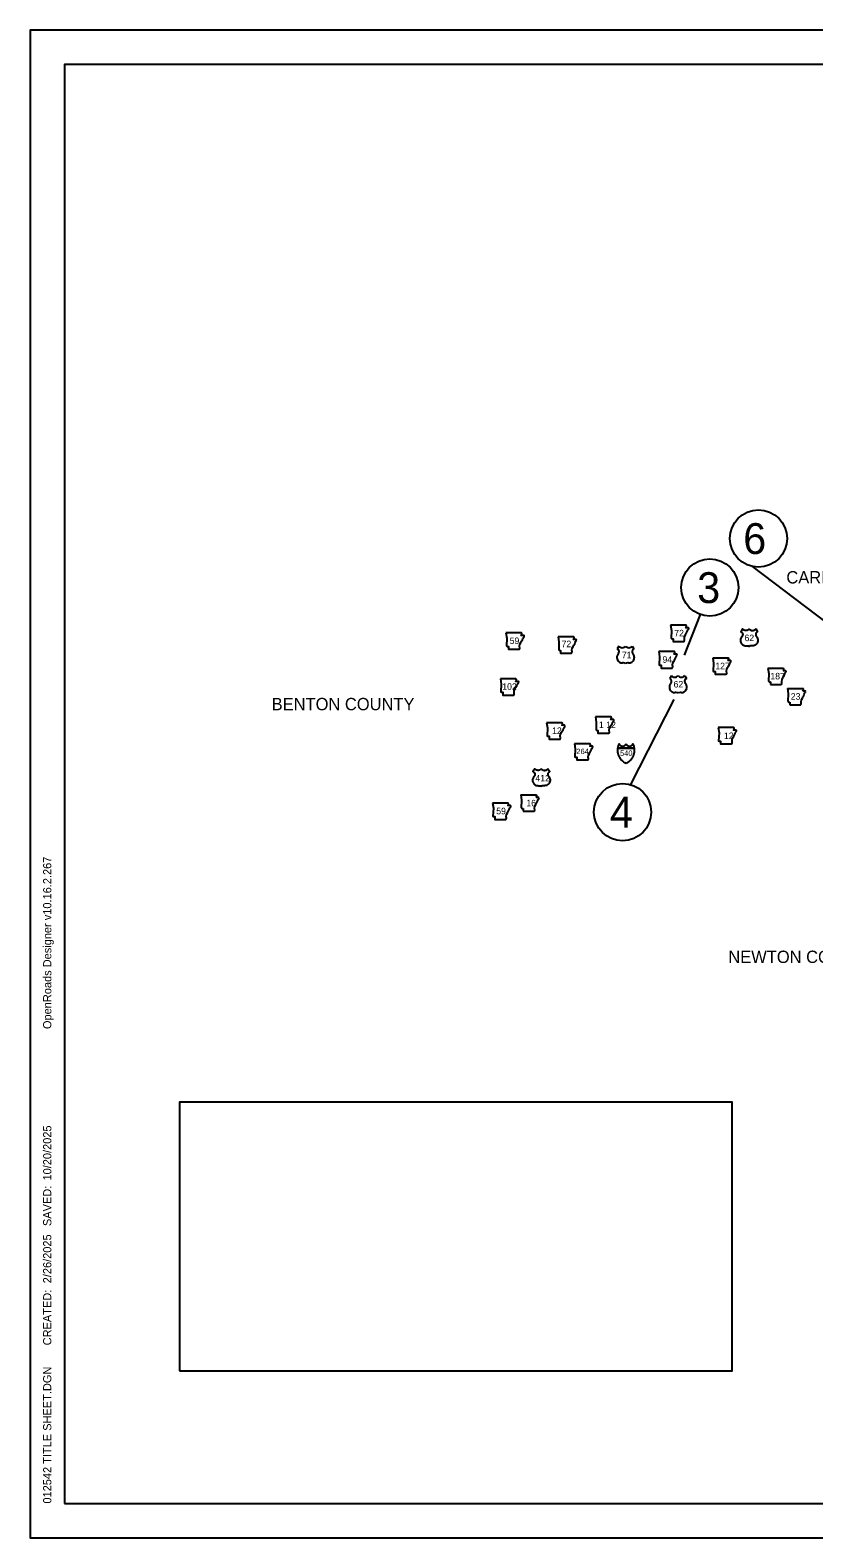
# Model space of a CAD drawing. Extents: x -819161 to 80911, y -6604 to 768454.
# Drawn here: x 35278 to 41002, y -340 to 10660 of the extents above; entities that cross this region are included whole.
import ezdxf

# ---------------------------------------------------------------- set-up
doc = ezdxf.new("R2010")
doc.units = 0
for name, color, linetype in [('Default', 7, 'Continuous'), ('DSN_BRDG_Annotation', 7, 'Continuous'), ('DSN_DRFT_Junk-No-Plot', 7, 'Continuous'), ('Level 21', 7, 'Continuous'), ('Level 22', 7, 'Continuous'), ('Level 23', 7, 'Continuous'), ('SHET_Border-Lines', 7, 'Continuous'), ('SHET_Border-Text', 7, 'Continuous')]:
    doc.layers.add(name, color=color, linetype=linetype)

msp = doc.modelspace()

# ---------------------------------------------------------------- linework, layer by layer
at = {"layer": 'Default'}
msp.add_lwpolyline([(35278, 10660), (35278, -340), (52278, -340), (52278, 10660)], close=True, dxfattribs=at)
for points in [[(40548, 6748), (41494, 6034)], [(40171, 6396), (40054, 6101)], [(39665, 5155), (39981, 5777)]]:
    msp.add_lwpolyline(points, dxfattribs=at)
for centre in [(40597, 6951), (40242, 6593), (39605, 4955)]:
    msp.add_circle(centre, 209, dxfattribs=at)
at = {"layer": 'DSN_BRDG_Annotation'}
msp.add_lwpolyline([(36370, 878), (40406, 878), (40406, 2838), (36370, 2838)], close=True, dxfattribs=at)
at = {"layer": 'DSN_DRFT_Junk-No-Plot'}
msp.add_lwpolyline([(35278, -340), (52278, -340), (52278, 10660), (35278, 10660)], close=True, dxfattribs=at)
at = {"layer": 'Level 21'}
for p, q in [((40666, 6004), (40672, 5966)), ((40672, 5966), (40670, 5909)), ((40776, 5934), (40780, 5943)), ((40778, 5985), (40783, 5994)), ((40798, 5985), (40778, 5985)), ((40780, 5943), (40786, 5952)), ((40783, 6000), (40781, 6004)), ((40783, 5994), (40783, 6000)), ((40786, 5952), (40790, 5963)), ((40790, 5963), (40793, 5971)), ((40793, 5971), (40799, 5978)), ((40800, 5982), (40798, 5985)), ((40799, 5978), (40800, 5982)), ((40670, 5909), (40675, 5906)), ((40675, 5906), (40684, 5906)), ((40684, 5906), (40684, 5885)), ((40684, 5885), (40764, 5885)), ((40764, 5885), (40768, 5893)), ((40767, 5907), (40769, 5922)), ((40768, 5893), (40767, 5907)), ((40769, 5922), (40776, 5934)), ((40809, 5857), (40814, 5819)), ((40920, 5838), (40925, 5847)), ((40940, 5838), (40920, 5838)), ((40925, 5853), (40923, 5857)), ((40925, 5847), (40925, 5853)), ((40936, 5824), (40941, 5831)), ((40943, 5835), (40940, 5838)), ((40941, 5831), (40943, 5835)), ((40814, 5819), (40812, 5762)), ((40812, 5762), (40817, 5758)), ((40817, 5758), (40826, 5758)), ((40826, 5758), (40826, 5738)), ((40826, 5738), (40906, 5738)), ((40906, 5738), (40910, 5746)), ((40909, 5760), (40911, 5775)), ((40910, 5746), (40909, 5760)), ((40911, 5775), (40918, 5787)), ((40918, 5787), (40922, 5796)), ((40922, 5796), (40929, 5805)), ((40929, 5805), (40932, 5816)), ((40932, 5816), (40936, 5824)), ((38862, 5081), (38867, 5043)), ((38973, 5062), (38978, 5071)), ((38993, 5062), (38973, 5062)), ((38978, 5077), (38976, 5081)), ((38978, 5071), (38978, 5077)), ((38996, 5059), (38993, 5062)), ((38867, 5043), (38865, 4985)), ((38865, 4985), (38870, 4982)), ((38870, 4982), (38879, 4982)), ((38879, 4982), (38879, 4962)), ((38879, 4962), (38959, 4962)), ((38959, 4962), (38963, 4970)), ((38962, 4983), (38964, 4999)), ((38963, 4970), (38962, 4983)), ((38964, 4999), (38971, 5011)), ((38971, 5011), (38975, 5019)), ((38975, 5019), (38982, 5029)), ((38982, 5029), (38985, 5039)), ((38985, 5039), (38989, 5047)), ((38989, 5047), (38994, 5054)), ((38994, 5054), (38996, 5059))]:
    msp.add_line(p, q, dxfattribs=at)
for points in [[(39955, 6319), (39961, 6281), (39959, 6223), (39964, 6220), (39973, 6220), (39973, 6199), (40053, 6199), (40057, 6208), (40056, 6221), (40058, 6236), (40065, 6248), (40069, 6257), (40075, 6267), (40079, 6277), (40082, 6285), (40088, 6292), (40089, 6296), (40087, 6300), (40067, 6300), (40072, 6308), (40072, 6314), (40070, 6319)], [(38753, 6263), (38759, 6225), (38756, 6167), (38761, 6164), (38771, 6164), (38771, 6143), (38851, 6143), (38855, 6152), (38853, 6165), (38855, 6180), (38862, 6192), (38867, 6201), (38873, 6211), (38877, 6221), (38880, 6229), (38886, 6236), (38887, 6240), (38885, 6244), (38865, 6244), (38869, 6252), (38870, 6258), (38867, 6263)], [(39135, 6234), (39140, 6196), (39138, 6138), (39143, 6135), (39152, 6135), (39152, 6114), (39232, 6114), (39236, 6123), (39235, 6136), (39237, 6151), (39244, 6163), (39248, 6172), (39255, 6182), (39258, 6192), (39262, 6200), (39267, 6207), (39268, 6212), (39266, 6215), (39246, 6215), (39251, 6224), (39251, 6229), (39249, 6234)], [(39870, 6126), (39875, 6088), (39873, 6030), (39878, 6027), (39887, 6027), (39887, 6006), (39967, 6006), (39971, 6015), (39970, 6028), (39972, 6043), (39979, 6055), (39983, 6064), (39989, 6074), (39993, 6084), (39996, 6092), (40002, 6099), (40003, 6103), (40001, 6107), (39981, 6107), (39986, 6116), (39986, 6121), (39984, 6126)], [(40263, 6079), (40269, 6041), (40266, 5983), (40271, 5980), (40281, 5980), (40281, 5960), (40361, 5960), (40365, 5968), (40363, 5982), (40365, 5997), (40372, 6009), (40377, 6018), (40383, 6027), (40387, 6037), (40390, 6046), (40396, 6053), (40397, 6057), (40394, 6060), (40375, 6060), (40379, 6069), (40380, 6075), (40377, 6079)], [(38712, 5928), (38718, 5889), (38715, 5832), (38720, 5829), (38730, 5829), (38730, 5808), (38810, 5808), (38813, 5816), (38812, 5830), (38814, 5845), (38821, 5857), (38825, 5866), (38832, 5875), (38836, 5886), (38839, 5894), (38844, 5901), (38846, 5905), (38843, 5908), (38824, 5908), (38828, 5917), (38829, 5923), (38826, 5927)], [(39408, 5650), (39413, 5612), (39411, 5555), (39416, 5551), (39425, 5551), (39425, 5531), (39505, 5531), (39509, 5539), (39508, 5553), (39510, 5568), (39517, 5580), (39521, 5589), (39528, 5598), (39531, 5609), (39535, 5617), (39540, 5624), (39541, 5628), (39539, 5631), (39519, 5631), (39524, 5640), (39524, 5646), (39522, 5650)], [(39050, 5607), (39056, 5569), (39053, 5511), (39058, 5508), (39068, 5508), (39068, 5488), (39148, 5488), (39152, 5496), (39150, 5509), (39152, 5525), (39159, 5537), (39164, 5545), (39170, 5555), (39174, 5565), (39177, 5573), (39183, 5580), (39184, 5585), (39181, 5588), (39162, 5588), (39166, 5597), (39167, 5603), (39164, 5607)], [(40303, 5571), (40309, 5533), (40306, 5475), (40312, 5472), (40321, 5472), (40321, 5452), (40401, 5452), (40405, 5460), (40404, 5474), (40405, 5489), (40412, 5501), (40417, 5510), (40423, 5519), (40427, 5529), (40430, 5538), (40436, 5545), (40437, 5549), (40435, 5552), (40415, 5552), (40419, 5561), (40420, 5567), (40417, 5571)], [(39254, 5454), (39259, 5416), (39257, 5358), (39262, 5355), (39271, 5355), (39271, 5335), (39351, 5335), (39355, 5343), (39354, 5356), (39356, 5371), (39363, 5383), (39367, 5392), (39373, 5402), (39377, 5412), (39380, 5420), (39386, 5427), (39387, 5432), (39385, 5435), (39365, 5435), (39370, 5444), (39370, 5449), (39368, 5454)], [(38655, 5021), (38661, 4983), (38658, 4925), (38663, 4922), (38673, 4922), (38673, 4901), (38753, 4901), (38756, 4910), (38755, 4923), (38757, 4938), (38764, 4950), (38769, 4959), (38775, 4969), (38779, 4979), (38782, 4987), (38788, 4994), (38789, 4998), (38786, 5002), (38767, 5002), (38771, 5011), (38772, 5016), (38769, 5021)]]:
    msp.add_lwpolyline(points, close=True, dxfattribs=at)
for points in [[(40666, 6004), (40781, 6004)], [(40809, 5857), (40923, 5857)], [(38862, 5081), (38976, 5081)]]:
    msp.add_lwpolyline(points, dxfattribs=at)
at = {"layer": 'Level 22'}
for p, q in [((39578, 6166), (39565, 6146)), ((39675, 6166), (39688, 6146)), ((39962, 5950), (39949, 5930)), ((40059, 5950), (40071, 5930))]:
    msp.add_line(p, q, dxfattribs=at)
for points in [[(40529, 6291), (40529, 6290), (40528, 6289), (40526, 6288), (40525, 6287), (40524, 6286), (40523, 6285), (40521, 6284), (40520, 6283), (40518, 6282), (40516, 6282), (40514, 6281), (40513, 6281), (40511, 6280), (40509, 6280), (40508, 6280), (40506, 6280), (40504, 6280), (40503, 6280), (40501, 6280), (40500, 6280), (40498, 6281), (40497, 6281), (40495, 6282), (40493, 6282), (40491, 6283), (40490, 6284), (40489, 6284), (40487, 6285), (40486, 6286), (40485, 6287), (40484, 6288), (40483, 6289), (40482, 6290), (40481, 6291), (40468, 6271), (40469, 6270), (40470, 6270), (40471, 6269), (40473, 6268), (40474, 6267), (40475, 6266), (40476, 6265), (40477, 6264), (40478, 6263), (40478, 6262), (40479, 6261), (40480, 6260), (40480, 6259), (40481, 6257), (40481, 6255), (40482, 6254), (40482, 6252), (40482, 6251), (40482, 6249), (40482, 6248), (40482, 6247), (40481, 6246), (40481, 6244), (40481, 6243), (40480, 6242), (40479, 6240), (40478, 6238), (40477, 6237), (40476, 6236), (40475, 6234), (40474, 6233), (40473, 6231), (40472, 6230), (40472, 6229), (40471, 6227), (40470, 6226), (40469, 6224), (40469, 6223), (40468, 6222), (40468, 6220), (40467, 6218), (40467, 6216), (40466, 6214), (40466, 6213), (40466, 6211), (40466, 6209), (40466, 6207), (40466, 6205), (40466, 6203), (40466, 6201), (40467, 6199), (40467, 6198), (40468, 6197), (40468, 6195), (40469, 6192), (40470, 6191), (40471, 6189), (40471, 6187), (40473, 6185), (40474, 6183), (40475, 6182), (40477, 6180), (40478, 6178), (40480, 6177), (40481, 6176)], [(40529, 6291), (40530, 6290), (40531, 6289), (40532, 6288), (40534, 6287), (40535, 6286), (40536, 6285), (40538, 6284), (40539, 6283), (40541, 6282), (40543, 6282), (40545, 6281), (40546, 6281), (40548, 6280), (40550, 6280), (40551, 6280), (40553, 6280), (40555, 6280), (40556, 6280), (40558, 6280), (40559, 6280), (40561, 6281), (40562, 6281), (40564, 6282), (40566, 6282), (40568, 6283), (40569, 6284), (40570, 6284), (40572, 6285), (40573, 6286), (40574, 6287), (40575, 6288), (40576, 6289), (40577, 6290), (40578, 6291), (40591, 6271), (40590, 6270), (40589, 6270), (40588, 6269), (40586, 6268), (40585, 6267), (40584, 6266), (40583, 6265), (40582, 6264), (40581, 6263), (40581, 6262), (40580, 6261), (40579, 6260), (40579, 6259), (40578, 6257), (40578, 6255), (40577, 6254), (40577, 6252), (40577, 6251), (40577, 6249), (40577, 6248), (40577, 6247), (40578, 6246), (40578, 6244), (40578, 6243), (40579, 6242), (40580, 6240), (40581, 6238), (40582, 6237), (40583, 6236), (40584, 6234), (40585, 6233), (40586, 6231), (40587, 6230), (40587, 6229), (40588, 6227), (40589, 6226), (40590, 6224), (40590, 6223), (40591, 6222), (40591, 6220), (40592, 6218), (40592, 6216), (40593, 6214), (40593, 6213), (40593, 6211), (40593, 6209), (40593, 6207), (40593, 6205), (40593, 6203), (40593, 6201), (40592, 6199), (40592, 6198), (40591, 6197), (40591, 6195), (40590, 6192), (40589, 6191), (40588, 6189), (40587, 6187), (40586, 6185), (40585, 6183), (40584, 6182), (40582, 6180), (40581, 6178), (40579, 6177), (40578, 6176)], [(40481, 6176), (40483, 6174), (40485, 6173), (40488, 6172), (40490, 6171), (40493, 6170), (40495, 6170), (40497, 6169), (40499, 6169), (40502, 6168), (40505, 6168), (40507, 6168), (40509, 6168), (40511, 6168), (40513, 6168), (40515, 6168), (40517, 6168), (40518, 6167), (40520, 6167), (40522, 6167), (40523, 6167), (40524, 6167), (40525, 6166), (40526, 6166), (40527, 6165), (40528, 6165), (40528, 6164), (40529, 6163), (40529, 6162)], [(40578, 6176), (40576, 6174), (40574, 6173), (40571, 6172), (40569, 6171), (40566, 6170), (40564, 6170), (40562, 6169), (40560, 6169), (40557, 6168), (40554, 6168), (40552, 6168), (40550, 6168), (40548, 6168), (40546, 6168), (40544, 6168), (40542, 6168), (40541, 6167), (40539, 6167), (40537, 6167), (40536, 6167), (40535, 6167), (40534, 6166), (40533, 6166), (40532, 6165), (40531, 6165), (40531, 6164), (40530, 6163), (40529, 6162)], [(39012, 5271), (39011, 5269), (39010, 5268), (39009, 5267), (39007, 5266), (39006, 5266), (39005, 5265), (39004, 5264), (39002, 5263), (39000, 5262), (38998, 5261), (38996, 5261), (38995, 5260), (38993, 5260), (38992, 5260), (38990, 5259), (38988, 5259), (38986, 5259), (38985, 5259), (38984, 5260), (38982, 5260), (38980, 5260), (38979, 5261), (38977, 5261), (38975, 5262), (38974, 5263), (38972, 5263), (38971, 5264), (38969, 5265), (38968, 5266), (38967, 5267), (38966, 5268), (38965, 5269), (38964, 5270), (38963, 5271), (38950, 5251), (38951, 5250), (38952, 5249), (38953, 5249), (38955, 5247), (38956, 5246), (38957, 5246), (38958, 5245), (38959, 5243), (38960, 5243), (38960, 5242), (38961, 5241), (38962, 5239), (38963, 5238), (38963, 5237), (38963, 5235), (38964, 5233), (38964, 5232), (38964, 5230), (38964, 5229), (38964, 5228), (38964, 5227), (38963, 5225), (38963, 5224), (38963, 5223), (38962, 5221), (38961, 5219), (38960, 5218), (38959, 5217), (38958, 5215), (38957, 5214), (38956, 5212), (38955, 5211), (38954, 5210), (38954, 5208), (38953, 5207), (38952, 5205), (38952, 5204), (38951, 5203), (38951, 5201), (38950, 5199), (38949, 5198), (38949, 5196), (38948, 5194), (38948, 5192), (38948, 5190), (38948, 5188), (38948, 5187), (38948, 5185), (38948, 5183), (38948, 5181), (38949, 5179), (38949, 5178), (38950, 5176), (38950, 5174), (38951, 5172), (38952, 5170), (38953, 5168), (38954, 5167), (38955, 5165), (38956, 5163), (38957, 5161), (38959, 5160), (38961, 5158), (38962, 5156), (38964, 5155)], [(39012, 5271), (39013, 5269), (39014, 5268), (39015, 5267), (39016, 5266), (39017, 5266), (39018, 5265), (39020, 5264), (39021, 5263), (39023, 5262), (39025, 5261), (39027, 5261), (39029, 5260), (39030, 5260), (39032, 5260), (39033, 5259), (39035, 5259), (39037, 5259), (39038, 5259), (39040, 5260), (39041, 5260), (39043, 5260), (39044, 5261), (39046, 5261), (39048, 5262), (39050, 5263), (39051, 5263), (39052, 5264), (39054, 5265), (39055, 5266), (39056, 5267), (39057, 5268), (39058, 5269), (39059, 5270), (39060, 5271), (39073, 5251), (39072, 5250), (39071, 5249), (39070, 5249), (39068, 5247), (39067, 5246), (39066, 5246), (39065, 5245), (39064, 5243), (39064, 5243), (39063, 5242), (39062, 5241), (39061, 5239), (39061, 5238), (39060, 5237), (39060, 5235), (39059, 5233), (39059, 5232), (39059, 5230), (39059, 5229), (39059, 5228), (39060, 5227), (39060, 5225), (39060, 5224), (39061, 5223), (39061, 5221), (39062, 5219), (39063, 5218), (39064, 5217), (39065, 5215), (39066, 5214), (39067, 5212), (39068, 5211), (39069, 5210), (39069, 5208), (39070, 5207), (39071, 5205), (39072, 5204), (39072, 5203), (39073, 5201), (39073, 5199), (39074, 5198), (39074, 5196), (39075, 5194), (39075, 5192), (39075, 5190), (39075, 5188), (39075, 5187), (39075, 5185), (39075, 5183), (39075, 5181), (39074, 5179), (39074, 5178), (39074, 5176), (39073, 5174), (39072, 5172), (39071, 5170), (39071, 5168), (39070, 5167), (39068, 5165), (39067, 5163), (39066, 5161), (39065, 5160), (39063, 5158), (39061, 5156), (39060, 5155)], [(38964, 5155), (38965, 5154), (38967, 5153), (38970, 5152), (38973, 5150), (38975, 5150), (38977, 5149), (38979, 5149), (38982, 5148), (38984, 5148), (38987, 5148), (38989, 5147), (38991, 5147), (38993, 5147), (38995, 5147), (38997, 5147), (38999, 5147), (39000, 5147), (39002, 5147), (39004, 5147), (39005, 5146), (39006, 5146), (39008, 5146), (39008, 5145), (39009, 5145), (39010, 5144), (39010, 5144), (39011, 5143), (39012, 5142)], [(39060, 5155), (39058, 5154), (39056, 5153), (39054, 5152), (39051, 5150), (39048, 5150), (39046, 5149), (39044, 5149), (39042, 5148), (39039, 5148), (39036, 5148), (39034, 5147), (39032, 5147), (39030, 5147), (39028, 5147), (39026, 5147), (39025, 5147), (39023, 5147), (39021, 5147), (39019, 5147), (39018, 5146), (39017, 5146), (39016, 5146), (39015, 5145), (39014, 5145), (39014, 5144), (39013, 5144), (39012, 5143), (39012, 5142)]]:
    msp.add_lwpolyline(points, dxfattribs=at)
for centre, radius, start, end in [((39602, 6186), 31.6, 220.075, 319.6701), ((39651, 6186), 31.6, 220.3299, 319.925), ((39598, 6083), 35.6, 160.9576, 197.3819), ((39604, 6083), 41.2, 195.1074, 237.1312), ((39548, 6117), 33.7, 30.7809, 59.9883), ((39616, 6078), 53.9, 138.9565, 162.6913), ((39556, 6126), 23.1, 328.8105, 21.2108), ((39649, 6083), 41.2, 302.8688, 344.8926), ((39697, 6126), 23.1, 158.7892, 211.1895), ((39705, 6117), 33.7, 120.0117, 149.2191), ((39637, 6078), 53.9, 17.3087, 41.0435), ((39655, 6083), 35.6, 342.6181, 19.0424), ((39605, 6096), 53, 244.0771, 269.5779), ((39606, 5946), 97, 81.1942, 90.9539), ((39618, 6033), 9.29, 28.0342, 72.9864), ((39635, 6033), 9.29, 107.0136, 151.9658), ((39647, 5946), 97, 89.0461, 98.8058), ((39648, 6096), 53, 270.4221, 295.9229), ((39986, 5971), 31.6, 220.075, 319.6701), ((40034, 5971), 31.6, 220.3299, 319.925), ((39982, 5867), 35.6, 160.9576, 197.3819), ((40000, 5863), 53.9, 138.9565, 162.6913), ((39988, 5867), 41.2, 195.1074, 237.1312), ((39932, 5901), 33.7, 30.7809, 59.9883), ((39939, 5910), 23.1, 328.8105, 21.2108), ((39989, 5880), 53, 244.0771, 269.5779), ((40032, 5880), 53, 270.4221, 295.9229), ((40033, 5867), 41.2, 302.8688, 344.8926), ((40081, 5910), 23.1, 158.7892, 211.1895), ((40088, 5901), 33.7, 120.0117, 149.2191), ((40021, 5863), 53.9, 17.3087, 41.0435), ((40038, 5867), 35.6, 342.6181, 19.0424), ((39990, 5730), 97, 81.1942, 90.9539), ((40002, 5817), 9.29, 28.0342, 72.9864), ((40018, 5817), 9.29, 107.0136, 151.9658), ((40031, 5730), 97, 89.0461, 98.8058)]:
    msp.add_arc(centre, radius, start, end, dxfattribs=at)
at = {"layer": 'Level 23'}
for points in [[(39630, 5310), (39625, 5312), (39620, 5315), (39615, 5319), (39611, 5322), (39606, 5326), (39604, 5328), (39601, 5330), (39599, 5332), (39597, 5335), (39595, 5337), (39593, 5340), (39591, 5342), (39590, 5345), (39588, 5347), (39587, 5349), (39586, 5351), (39584, 5353), (39583, 5355), (39582, 5358), (39580, 5360), (39579, 5363), (39578, 5365), (39577, 5367), (39576, 5370), (39576, 5372), (39575, 5375), (39574, 5377), (39573, 5380), (39573, 5382), (39572, 5384), (39572, 5386), (39571, 5389), (39571, 5392), (39570, 5395), (39570, 5398), (39570, 5401), (39570, 5404), (39570, 5407), (39570, 5410), (39570, 5412), (39570, 5414), (39570, 5415), (39571, 5418), (39571, 5422)], [(39571, 5422), (39571, 5424), (39572, 5427), (39572, 5430), (39573, 5432), (39574, 5435), (39574, 5438), (39575, 5440), (39576, 5443), (39577, 5446), (39578, 5449), (39579, 5451), (39580, 5453), (39581, 5451), (39582, 5449), (39583, 5447), (39585, 5445), (39586, 5444), (39587, 5443), (39588, 5442), (39590, 5441), (39592, 5439), (39595, 5438), (39597, 5437), (39600, 5437), (39602, 5436), (39605, 5436), (39607, 5436), (39609, 5436), (39611, 5436), (39613, 5437), (39615, 5438), (39617, 5439), (39619, 5440), (39621, 5441), (39624, 5443), (39625, 5445), (39627, 5447), (39628, 5449), (39629, 5451), (39630, 5453)], [(39689, 5422), (39571, 5422)], [(39571, 5422), (39689, 5422)], [(39630, 5453), (39631, 5451), (39632, 5449), (39633, 5447), (39635, 5445), (39637, 5443), (39639, 5441), (39641, 5440), (39643, 5439), (39646, 5438), (39648, 5437), (39650, 5436), (39651, 5436), (39654, 5436), (39655, 5436), (39658, 5436), (39661, 5437), (39663, 5437), (39665, 5438), (39668, 5439), (39670, 5441), (39672, 5442), (39673, 5443), (39675, 5444), (39676, 5445), (39677, 5447), (39678, 5449), (39679, 5451), (39680, 5453), (39681, 5451), (39682, 5449), (39683, 5446), (39684, 5443), (39685, 5440), (39686, 5438), (39687, 5435), (39687, 5432), (39688, 5430), (39688, 5427), (39689, 5424), (39689, 5422)], [(39689, 5422), (39690, 5418), (39690, 5415), (39690, 5414), (39690, 5412), (39690, 5410), (39690, 5407), (39690, 5404), (39690, 5401), (39690, 5398), (39690, 5395), (39689, 5392), (39689, 5389), (39688, 5386), (39688, 5384), (39687, 5382), (39687, 5380), (39686, 5377), (39685, 5375), (39685, 5372), (39684, 5370), (39683, 5367), (39682, 5365), (39681, 5363), (39680, 5360), (39679, 5358), (39677, 5355), (39676, 5353), (39675, 5351), (39674, 5349), (39672, 5347), (39671, 5345), (39669, 5342), (39667, 5340), (39665, 5337), (39663, 5335), (39661, 5332), (39659, 5330), (39657, 5328), (39655, 5326), (39650, 5322), (39645, 5319), (39640, 5315), (39635, 5312), (39630, 5310)]]:
    msp.add_lwpolyline(points, dxfattribs=at)
at = {"layer": 'SHET_Border-Lines'}
msp.add_lwpolyline([(35528, -90), (52028, -90), (52028, 10410), (35528, 10410)], close=True, dxfattribs=at)
msp.add_lwpolyline([(35528, -90), (52028, -90), (52028, 10410), (35528, 10410)], close=True, dxfattribs=at)

# ---------------------------------------------------------------- texts
at = {"layer": 'Default'}
for s, height, p in [('6', 225, (40486, 6838)), ('CARROLL COUNTY', 90, (40801, 6623)), ('3', 225, (40150, 6480)), ('BENTON COUNTY', 90, (37042, 5698)), ('4', 225, (39512, 4842)), ('NEWTON COUNTY', 90, (40377, 3854))]:
    msp.add_text(s, height=height, dxfattribs=at).set_placement(p)
at = {"layer": 'Level 21'}
for s, height, p in [('72', 47.5, (39982, 6237)), ('59', 47.5, (38780, 6181)), ('72', 47.5, (39159, 6158)), ('94', 47.5, (39896, 6044)), ('127', 47.5, (40282, 5997)), ('187', 47.5, (40684, 5923)), ('102', 47.5, (38726, 5847)), ('23', 47.5, (40833, 5775)), ('1 12', 47.5, (39432, 5568)), ('12', 47.5, (39090, 5525)), ('12', 47.5, (40345, 5488)), ('264', 39.6, (39267, 5378)), ('59', 47.5, (38682, 4939)), ('16', 47.5, (38902, 4997))]:
    msp.add_text(s, height=height, dxfattribs=at).set_placement(p)
at = {"layer": 'Level 22'}
for s, p in [('62', (40495, 6202)), ('71', (39599, 6077)), ('62', (39977, 5864)), ('412', (38968, 5179))]:
    msp.add_text(s, height=47.5, dxfattribs=at).set_placement(p)
at = {"layer": 'Level 23'}
msp.add_text('540', height=39.6, dxfattribs=at).set_placement((39586, 5365))
at = {"layer": 'SHET_Border-Text'}
for s, p in [('OpenRoads Designer v10.16.2.267', (35433, 3372)), ('10/20/2025', (35433, 2267)), ('  SAVED: ', (35433, 1890)), ('2/26/2025', (35433, 1517)), ('     CREATED: ', (35433, 953)), ('012542 TITLE SHEET.DGN', (35433, -90))]:
    msp.add_text(s, height=60, rotation=90, dxfattribs=at).set_placement(p)

doc.saveas('drawing.dxf')
